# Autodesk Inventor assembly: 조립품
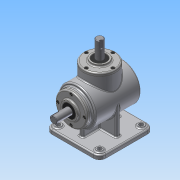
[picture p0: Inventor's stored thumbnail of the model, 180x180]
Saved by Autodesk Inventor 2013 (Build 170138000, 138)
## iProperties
Created: 2015-07
Part Number: 조립품
Document SubType Name: Assembly
Designer: ST4
Author: ST4
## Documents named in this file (14)
- C:\Users\ST4\Desktop\450705V1020\조립품.iam
- C:\Users\ST4\Desktop\450705V1020\본체.ipt
- C:\Users\ST4\Desktop\450705V1020\서브 축.ipt
- 서브 축.ipt
- C:\Users\ST4\Desktop\450705V1020\베어링 6203.ipt
- C:\Users\ST4\Desktop\450705V1020\커버.ipt
- C:\Users\ST4\Desktop\450705V1020\서브 베벨기어.ipt
- C:\Users\ST4\Desktop\450705V1020\키 4x4.ipt
- C:\Users\ST4\Desktop\450705V1020\오일실.ipt
- C:\Users\ST4\Desktop\450705V1020\메인 축.ipt
- 메인 축.ipt
- C:\Users\ST4\Desktop\450705V1020\메인 베벨기어.ipt
- C:\Users\ST4\Desktop\450705V1020\키 5x5.ipt
- C:\Users\ST4\Desktop\450705V1020\M4.ipt
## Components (8 placed, 1 different names)
1. M4:1
2. M4:3
3. M4:4
4. M4:5
5. M4:2
6. M4:6
7. M4:7
8. M4:8
